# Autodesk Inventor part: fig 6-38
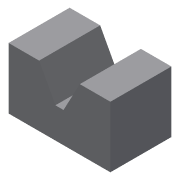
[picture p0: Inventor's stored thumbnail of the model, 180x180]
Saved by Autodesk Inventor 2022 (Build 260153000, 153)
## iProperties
Created: 2005-12
Part Number: fig 6-38
Document SubType Name: Modeling
Designer: CADCIM
Density: 1 g/cm^3
Material: Generic
Appearance: Default
Author: CADCIM
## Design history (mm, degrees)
sketch "Sketch1"
  geometry: L1 (10, 15)-(25, 15); L2 (25, 15)-(25, -15); L3 (25, -15)-(-25, -15); L4 (-25, -15)-(-25, 15); L5 (-25, 15)-(-10, 15); L6 (-10, 15)-(-2, 0); L7 (-2, 0)-(2, 0); L8 (2, 0)-(10, 15); 1 further point
  constraints: 16 end point, 3 equal length, 3 parallel, 1 collinear, 1 horizontal, 1 perpendicular, 1 other
  dimensions: "d0" = 50 distance of L2.end L3.end; "d1" = 25 distance from line of point (0, 0) L2; "d2" = 30 distance of L1.end L2.end; "d3" = 15 distance of L1.start L1.end; "d4" = 15 distance between parallel lines of L1 L7; "d5" = 4 distance of L6.end L7.end; "d6" = 15 distance from line of point (0, 0) L3
extrude "Extrusion1" new body sketch "Sketch1" stored distance "d7" = 30; taper "d8" = 0 deg
body "Solid1"
